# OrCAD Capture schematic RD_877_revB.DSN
size B
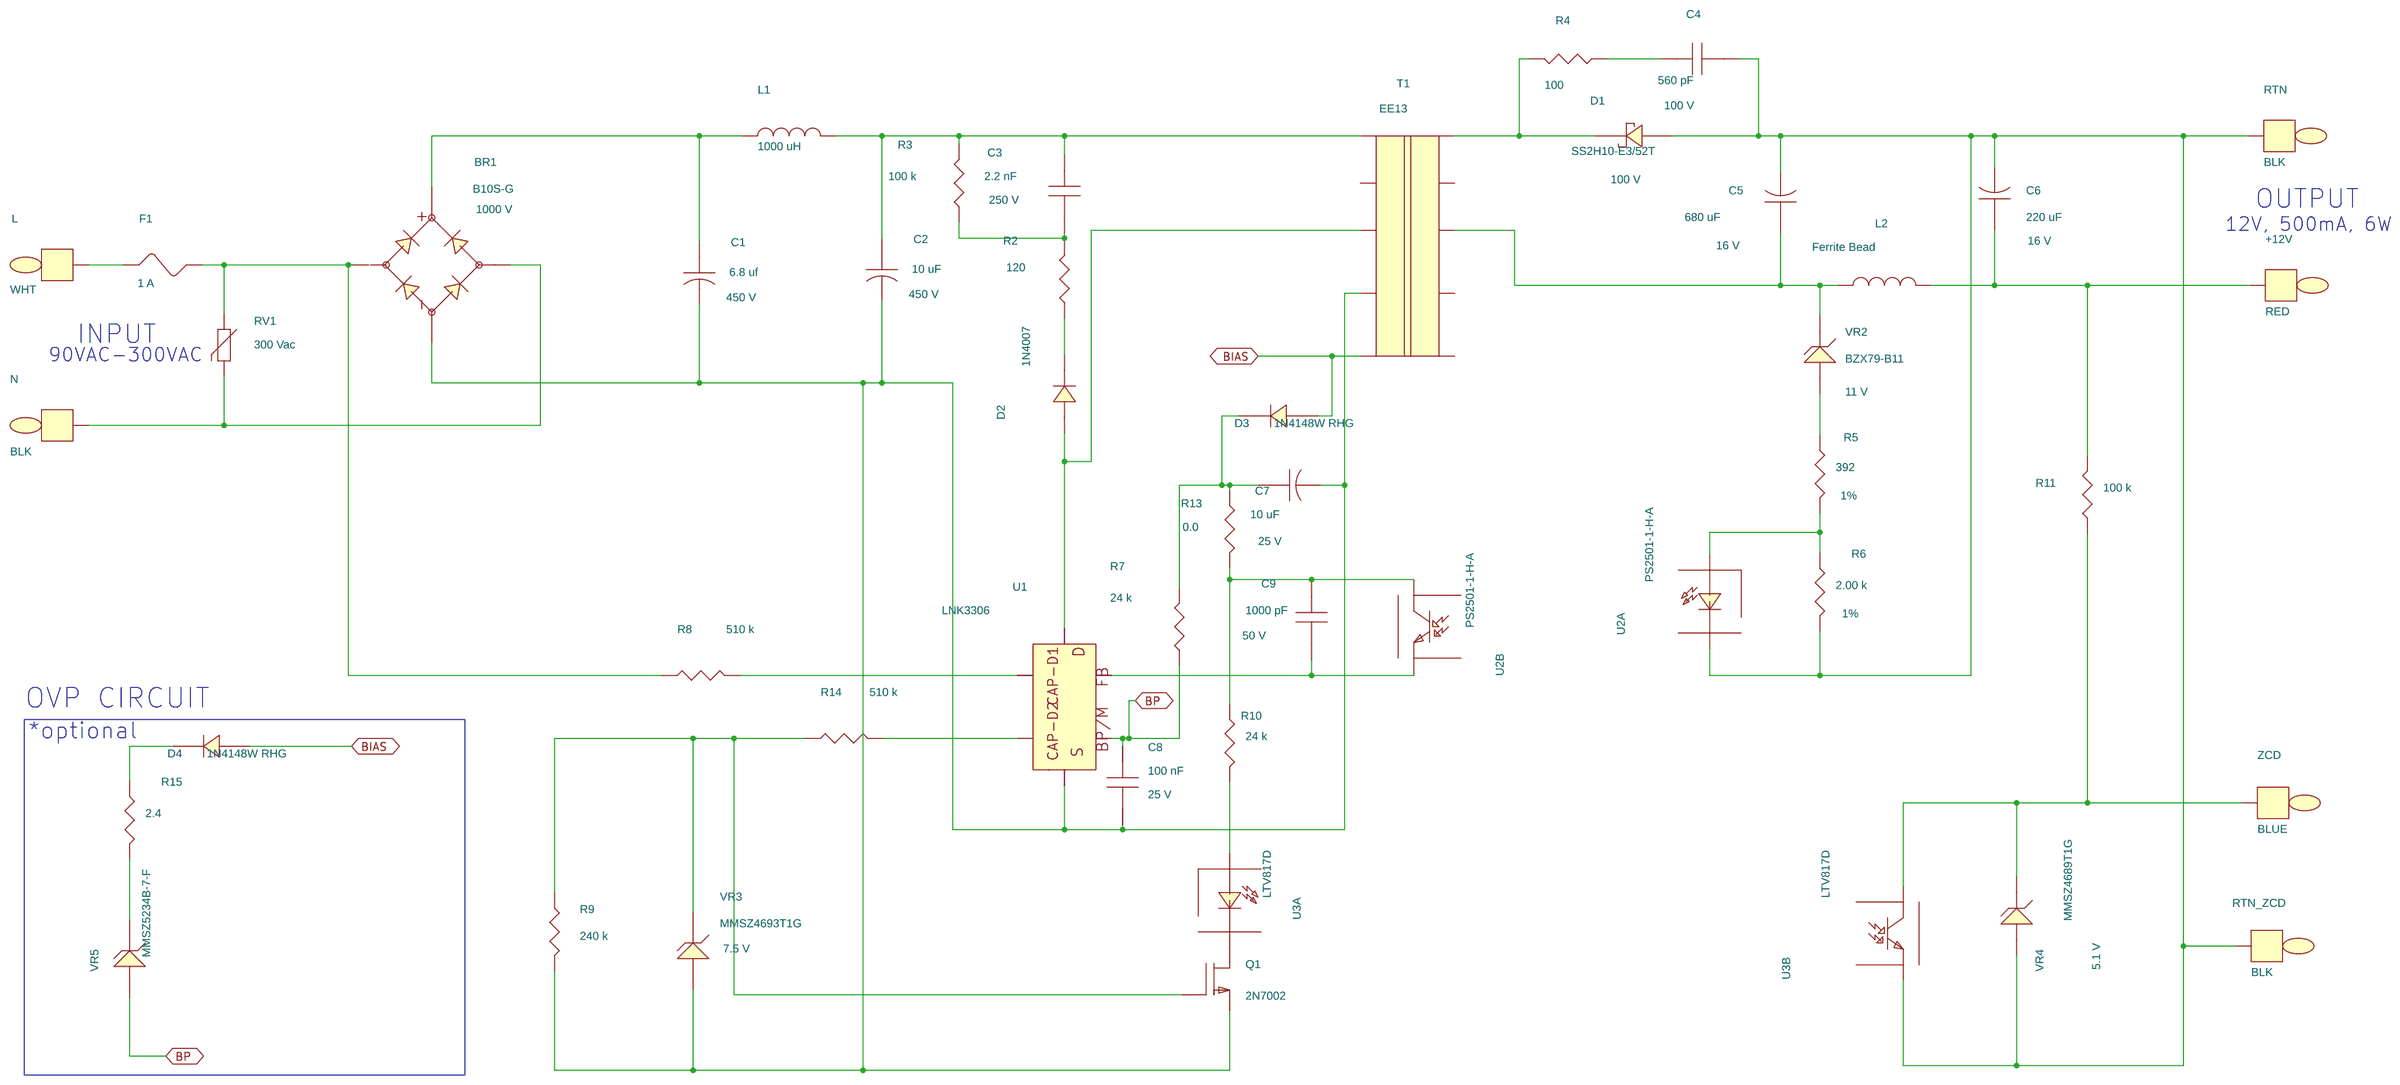
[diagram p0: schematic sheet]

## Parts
+12V  RED  [pitpkeystone100x100]
BR1  B10S-G  [pismsoic4]
C1  6.8 uf  [pipolcapcyld400ls200040]
C2  10 uF  [pipolcapcyld400ls200040]
C3  2.2 nF  [pismc0805]
C4  560 pF  [pismc0805]
C5  680 uF  [pipolcapcyld400ls200040]
C6  220 uF  [pipolcapcyld250ls100030]
C7  10 uF  [pipolcapclyd200ls80030]
C8  100 nF  [pismc0805]
C9  1000 pF  [pismc0603]
D1  SS2H10-E3/52T  [pismsmb]
D2  1N4007  [pidv200x110x040do41]
D3  1N4148W RHG  [pi_sm_sod-123_12]
D4  1N4148W RHG  [pi_sm_sod-123_12]
F1  1 A  [pi_rst_microfuse]
L  WHT  [pitpkeystone125x125]
L1  1000 uH  [pichoketokinvd216h413ls098d030]
L2  Ferrite Bead  [pi12wresd180ls675d040]
N  BLK  [pitpkeystone125x125]
Q1  2N7002  [pismsot23123_1]
R2  120  [pismr1206]
R3  100 k  [pismr1206]
R4  100  [pismr1206]
R5  392  [pismr0805]
R6  2.00 k  [pismr0805]
R7  24 k  [pismr0603]
R8  510 k  [pi14wvresd100ls100d030]
R9  240 k  [pismr1206]
R10  24 k  [pismr0603]
R11  100 k  [pismr0805]
R13  0.0  [pismr0805]
R14  510 k  [pi14wvresd100ls100d030]
R15  2.4  [pismr0603]
RTN  BLK  [pitpkeystone100x100]
RTN_ZCD  BLK  [pitpkeystone100x100]
RV1  300 Vac  [pidisc350x225ls240x140040]
T1  EE13  [pi_bobbin_ee13v_10p]
U1  LNK3306  [pismso8_nop3]
U2  PS2501-1-H-A  [pi_dip4]  (sections A,B)
U3  LTV817D  [pi_dip4]  (sections A,B)
VR2  BZX79-B11  [pidv200x080x030do35]
VR3  MMSZ4693T1G  [pi_sm_sod-123_12]
VR4  MMSZ4689T1G  [pi_sm_sod-123_12]
VR5  MMSZ5234B-7-F  [pi_sm_sod-123_12]
ZCD  BLUE  [pitpkeystone100x100]

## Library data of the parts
+12V = TESTPOINT: Part Number: 35-00080-00
BR1 = DIODE_BRIDGE_~~+-: ALT_SYMBOLS: pi_sm_soic4_slot; Disp_Voltage: 1000 V; FPLIST: pismsoic4,pi_sm_soic4_slot; Part Number: 15-00818-00
C1 = CAP_POL: Disp_Voltage: 450 V; Part Number: 20-01408-00; Voltage: 450 V
C2 = CAP_POL: ALT_SYMBOLS: pipolcapclyd395x630ls200030h; Disp_Voltage: 450 V; FPLIST: pipolcapcyld400ls200040,pipolcapclyd395x630ls200030h; Part Number: 20-01494-00; Voltage: 450 V
C3 = CAP_NP: Disp_Voltage: 250 V; Part Number: 20-08766-00; Voltage: 250 V
C4 = CAP_NP: Disp_Voltage: 100 V; Part Number: 20-09240-00; Voltage: 100 V
C5 = CAP_POL: ALT_SYMBOLS: pipolcapclyd395x630ls200030h; Disp_Voltage: 16 V; FPLIST: pipolcapcyld400ls200040,pipolcapclyd395x630ls200030h; Part Number: 20-00018-00; Voltage: 16 V
C6 = CAP_POL: Disp_Voltage: 16 V; Part Number: 20-00080-00; Voltage: 16 V
C7 = CAP_POL: ALT_SYMBOLS: pipolcapclyd200ls80030h; Disp_Voltage: 25 V; FPLIST: pipolcapclyd200ls80030,pipolcapclyd200ls80030h; Part Number: 20-01182-00; Voltage: 25 V
C8 = CAP_NP: Disp_Voltage: 25 V; Part Number: 20-08599-00; Voltage: 25 V
C9 = CAP_NP: Disp_Voltage: 50 V; Part Number: 20-09119-00; Voltage: 50 V
D1 = DIODE_SCHOTTKY: Disp_Voltage: 100 V; Part Number: 15-00995-00
D2 = DIODE: ALT_SYMBOLS: pidax475x125040do41,pidv200x110x040do41wbead,pidax390x125040do41; FPLIST: pidv200x110x040do41,pidax475x125040do41,pidv200x110x040do41wbead,pidax390x125040do41; Part Number: 15-00623-00
D3 D4 = DIODE: ALT_SYMBOLS: pi_sm_sod-123_12_1; FPLIST: pi_sm_sod-123_12,pi_sm_sod-123_12_1; Part Number: 15-01269-00
F1 = FUSE: ALT_SYMBOLS: pirstmicrofusehoz; FPLIST: pi_rst_microfuse,pirstmicrofusehoz; Part Number: 40-00053-00
L = TESTPOINT: Part Number: 35-00044-00
L1 = INDUCTOR: Part Number: 30-00020-00
L2 = INDUCTOR: ALT_SYMBOLS: pi12wvresd180ls150d040,pi12wvresd180ls200d040,pi12wvresd180ls250d040; FPLIST: pi12wresd180ls675d040,pi12wvresd180ls150d040,pi12wvresd180ls200d040,pi12wvresd180ls250d040; Part Number: 30-00143-00
N = TESTPOINT: Part Number: 35-00042-00
Q1 = FET_N_GSD: Part Number: 50-00103-00
R2 = R: Part Number: 05-01330-00
R3 = R: Part Number: 05-01400-00
R4 = R: Part Number: 05-01328-00
R5 = R: Disp_Tol: 1%; Part Number: 05-00645-00
R6 = R: Disp_Tol: 1%; Part Number: 05-03337-00
R7 R10 = R: Part Number: 05-01721-00
R8 R14 = R: ALT_SYMBOLS: pi14wvresd100ls125d030,pi14wvresd100ls150d030,pi14wvresd100ls200d030,pi14wvresd100ls300d030,pi14wresd100ls400d030,pi14wresd100ls500d030; FPLIST: pi14wvresd100ls100d030,pi14wvresd100ls125d030,pi14wvresd100ls150d030,pi14wvresd100ls200d030,pi14wvresd100ls300d030,pi14wresd100ls400d030,pi14wresd100ls500d030; Part Number: 05-02572-00
R9 = R: Part Number: 05-01409-00
R11 = R: Part Number: 05-01567-00
R13 = R: ALT_SYMBOLS: pismr0805_1; FPLIST: pismr0805,pismr0805_1; Part Number: 05-03159-00
R15 = R: Part Number: 05-01625-00
RTN RTN_ZCD = TESTPOINT: Part Number: 35-00079-00
RV1 = VARISTOR: Part Number: 85-00031-00
T1 = BEE13_10PINS_GENERIC: FPLIST: pi_bobbin_ee13v_10p,pi_bobbin_ee13h_10p_htc; Part Number: 25-00872-00
U1 = LNK-TNZ: Part Number: 10-01236-00
U2 = OPTO_A_B: Part Number: 53-00041-00
U3 = OPTO_A_B: Part Number: 53-00019-00
VR2 = DIODE_ZENER: ALT_SYMBOLS: pidax375x070030do35; Disp_Voltage: 11 V; FPLIST: pidv200x080x030do35,pidax375x070030do35; Part Number: 15-00232-00
VR3 = DIODE_ZENER: Disp_Voltage: 7.5 V; Part Number: 15-01578-00
VR4 = DIODE_ZENER: Disp_Voltage: 5.1 V; Part Number: 15-01195-00
VR5 = DIODE_ZENER: Part Number: 15-01083-00
ZCD = TESTPOINT: Part Number: 35-00397-00

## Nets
BIAS: D3.2 D4.2 T1.5
BP: C8.1 R7.1 U1.7 VR5.2
N4253666: C4.1 R4.1
N4253670: C4.2 C5.2 C6.2 D1.2 R6.2 RTN.1 RTN_ZCD.1 U2.2(C) U3.3(E) VR4.2
N4254079: BR1.4 C1.2 C2.2 C7.2 C8.2 Q1.2(S) R9.1 T1.4 U1.5 VR3.2
N4254091: C7.1 D3.1 R7.2 R13.2
N4254098: C2.1 C3.1 L1.2 R3.1 T1.1
N4254129: C3.2 R2.1 R3.2
N4254146: D2.1 R2.2
N4254163: D2.2 T1.3 U1.4
N4254668: C9.2 U1.8 U2.3(E)
N4254798: R5.1 VR2.2
N4254829: R5.2 R6.1 U2.1(A)
N4255085: BR1.3 C1.1 L1.1
N4255357: BR1.2 F1.2 R8.1 RV1.1
N4255389: F1.1 L.1
N4255403: BR1.1 N.1 RV1.2
N4255537: R8.2 U1.1
N4259135: Q1.1(G) R9.2 R14.1 VR3.1
N4259502: R10.2 U3.1(A)
N4259699: R11.2 U3.4(C) VR4.1 ZCD.1
N4266456: C9.1 R10.1 R13.1 U2.4(C)
N4272601: D1.1 R4.2 T1.10
N4274175: C5.1 L2.1 T1.8 VR2.1
N4274624: +12V.1 C6.1 L2.2 R11.1
N4282141: R14.2 U1.2
N4296647: D4.1 R15.1
N4296671: R15.2 VR5.1
N4298721: Q1.3(D) U3.2(C)

Not connected (* = marked no-connect by the designer): T1 2 6 7 9; U1 6

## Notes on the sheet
- OUTPUT
- 12V, 500mA, 6W
- INPUT
- 90VAC-300VAC
- OVP CIRCUIT
- *optional
